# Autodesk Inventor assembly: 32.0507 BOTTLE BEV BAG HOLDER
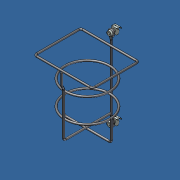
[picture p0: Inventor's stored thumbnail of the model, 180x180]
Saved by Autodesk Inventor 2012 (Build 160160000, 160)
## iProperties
Created: 2013-04
Part Number: 32.0507 BOTTLE BEV BAG HOLDER
Document SubType Name: Assembly
Designer: Admin
Author: Admin
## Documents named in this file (4)
- C:\Andys Backup Data\ANDY'S INVENTOR\INVENTOR LIBRARIES\PARTS LIBRARY\WORKSTATION\32.0507 BOTTLE BEV BAG HOLDER.iam
- C:\Andys Backup Data\ANDY'S INVENTOR\INVENTOR LIBRARIES\PARTS LIBRARY\WORKSTATION\SUBCOMPONENTS\32.0507 BOTTLE BEVERAGE BAG HOLDER WIRE.iam
- C:\Andys Backup Data\ANDY'S INVENTOR\INVENTOR LIBRARIES\PARTS LIBRARY\FASTENING ELEMENTS\SCREWS CAP\21.1238 M6X16.ipt
- C:\Andys Backup Data\ANDY'S INVENTOR\INVENTOR LIBRARIES\PARTS LIBRARY\FASTENING ELEMENTS\NUTS\21.1330_2 M6 SQUARE NUT POS FXG.ipt
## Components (5 placed, 3 different names)
1. 32.0507 BOTTLE BEVERAGE BAG HOLDER WIRE:1 [sub-assembly] — Mate:1, Flush:1, Mate:2, Flush:2
2. 21.1238  M6 x 16:1 — Mate:1, Flush:1, Mate:4, Mate:5
3. 21.1238  M6 x 16:2 — Mate:2, Flush:2, Mate:3, Mate:6
4. 21.1330_2 M6 SQUARE NUT POS FXG:1 — Mate:3, Mate:6, Angle:2
5. 21.1330_2 M6 SQUARE NUT POS FXG:2 — Mate:4, Mate:5, Angle:1
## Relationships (10: Mate 6, Flush 2, Angle 2)
- Mate:1: 32.0507 BOTTLE BEVERAGE BAG HOLDER WIRE:1 ↔ 21.1238  M6 x 16:1
- Flush:1: 32.0507 BOTTLE BEVERAGE BAG HOLDER WIRE:1 ↔ 21.1238  M6 x 16:1
- Mate:2: 32.0507 BOTTLE BEVERAGE BAG HOLDER WIRE:1 ↔ 21.1238  M6 x 16:2
- Flush:2: 32.0507 BOTTLE BEVERAGE BAG HOLDER WIRE:1 ↔ 21.1238  M6 x 16:2
- Mate:3: 21.1238  M6 x 16:2 ↔ 21.1330_2 M6 SQUARE NUT POS FXG:1
- Mate:4: 21.1238  M6 x 16:1 ↔ 21.1330_2 M6 SQUARE NUT POS FXG:2
- Mate:5: 21.1238  M6 x 16:1 ↔ 21.1330_2 M6 SQUARE NUT POS FXG:2
- Mate:6: 21.1238  M6 x 16:2 ↔ 21.1330_2 M6 SQUARE NUT POS FXG:1
- Angle:1: 21.1330_2 M6 SQUARE NUT POS FXG:2
- Angle:2: 21.1330_2 M6 SQUARE NUT POS FXG:1
